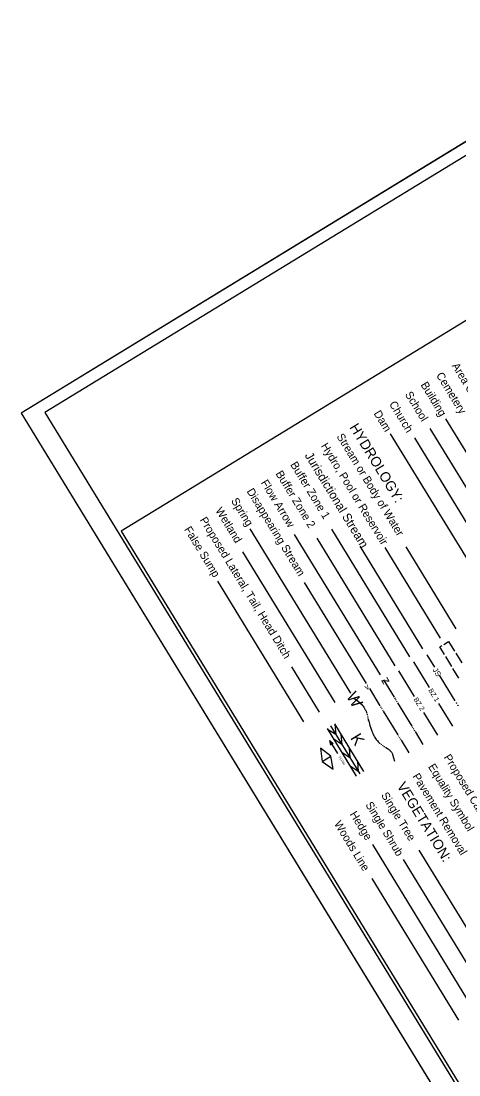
# Model space of a CAD drawing. Extents: x 1750583 to 1791140, y 783580 to 827376.
# Drawn here: x 1750583 to 1755844, y 799616 to 812289 of the extents above; entities that cross this region are included whole.
import ezdxf

# ---------------------------------------------------------------- set-up
doc = ezdxf.new("R2010")
doc.units = 0
for name, color, linetype in [('Sheet Cutting Line CELL', 7, 'Continuous'), ('Sheet Plot Border Inside CELL', 7, 'Continuous'), ('Sheet Plot Border Outside CELL', 7, 'Continuous'), ('Sheet Symbology CELL', 7, 'Continuous')]:
    doc.layers.add(name, color=color, linetype=linetype)

msp = doc.modelspace()

# ---------------------------------------------------------------- linework, layer by layer
at = {"layer": 'Sheet Cutting Line CELL'}
for p, q in [((1760908, 813883), (1750583, 807575)), ((1750583, 807575), (1760241, 791768))]:
    msp.add_line(p, q, dxfattribs=at)
at = {"layer": 'Sheet Plot Border Inside CELL'}
msp.add_lwpolyline([(1750868, 807581), (1760426, 791939), (1770330, 797990), (1760772, 813633)], close=True, dxfattribs=at)
at = {"layer": 'Sheet Plot Border Outside CELL'}
msp.add_lwpolyline([(1750583, 807575), (1760241, 791768), (1770566, 798076), (1760908, 813883)], close=True, dxfattribs=at)
at = {"layer": 'Sheet Symbology CELL'}
for p, q in [((1756879, 805555), (1755688, 807505)), ((1756316, 805211), (1755023, 807327)), ((1756692, 805441), (1755500, 807390)), ((1756504, 805326), (1755313, 807276)), ((1754544, 804207), (1753337, 806183)), ((1755256, 804642), (1754317, 806180)), ((1754902, 804426), (1753870, 806114)), ((1755079, 804534), (1754140, 806071)), ((1754356, 804093), (1753248, 805906)), ((1755412, 804738), (1754657, 805973)), ((1755624, 804867), (1754957, 805960)), ((1755812, 804982), (1755210, 805968)), ((1753981, 803863), (1752947, 805555)), ((1754732, 804322), (1753989, 805538)), ((1755661, 804792), (1755720, 804828)), ((1755720, 804828), (1755792, 804711)), ((1755757, 804529), (1755685, 804646)), ((1755806, 804687), (1755878, 804570)), ((1754168, 803978), (1753835, 804524)), ((1755297, 804584), (1755485, 804276)), ((1755119, 804475), (1755307, 804167)), ((1755843, 804388), (1755771, 804505)), ((1754769, 804261), (1754895, 804054)), ((1754939, 804365), (1755065, 804158)), ((1755071, 804149), (1755077, 804139)), ((1755083, 804130), (1755088, 804121)), ((1754901, 804045), (1754907, 804035)), ((1754913, 804026), (1754918, 804017)), ((1754924, 804007), (1754930, 803998)), ((1755094, 804111), (1755100, 804102)), ((1755106, 804092), (1755278, 803811)), ((1755771, 803809), (1755602, 804084)), ((1754749, 803913), (1754751, 803902)), ((1754935, 803989), (1755108, 803707)), ((1755592, 803701), (1755424, 803976)), ((1754260, 803782), (1754609, 803210)), ((1754365, 803709), (1754266, 803771)), ((1754302, 803812), (1754653, 803236)), ((1754348, 803837), (1754698, 803264)), ((1754353, 803828), (1754365, 803709)), ((1755283, 803801), (1755289, 803792)), ((1755295, 803783), (1755301, 803773)), ((1755306, 803764), (1755312, 803754)), ((1754290, 803637), (1754386, 803481)), ((1754290, 803637), (1754331, 803600)), ((1754290, 803637), (1754300, 803581)), ((1754437, 803589), (1754339, 803652)), ((1754426, 803709), (1754437, 803589)), ((1755113, 803698), (1755119, 803688)), ((1755125, 803679), (1755130, 803669)), ((1755136, 803660), (1755142, 803651)), ((1755148, 803641), (1755242, 803487)), ((1755318, 803745), (1755412, 803590)), ((1754306, 803449), (1754179, 803546)), ((1754179, 803546), (1754202, 803386)), ((1754524, 803550), (1754535, 803430)), ((1754906, 803594), (1754915, 803588)), ((1754924, 803581), (1754932, 803575)), ((1754202, 803386), (1754306, 803449)), ((1754202, 803386), (1754331, 803292)), ((1754331, 803292), (1754306, 803449)), ((1754535, 803430), (1754437, 803492)), ((1754625, 803383), (1754635, 803266)), ((1754635, 803266), (1754538, 803327)), ((1756029, 800391), (1754809, 802387)), ((1756405, 800620), (1755366, 802320)), ((1756217, 800505), (1755178, 802206)), ((1755841, 800276), (1754803, 801976))]:
    msp.add_line(p, q, dxfattribs=at)
msp.add_lwpolyline([(1770234, 798093), (1761631, 812173), (1751785, 806156), (1760388, 792077)], close=True, dxfattribs=at)
for points in [[(1755671, 804670), (1755614, 804763), (1755637, 804778)], [(1755457, 804668), (1755549, 804518)], [(1755607, 804423), (1755687, 804292)], [(1755687, 804292), (1755796, 804113)], [(1754581, 804146), (1754609, 804126), (1754636, 804106), (1754643, 804101), (1754654, 804092), (1754662, 804084), (1754674, 804073), (1754685, 804060), (1754693, 804049), (1754701, 804040), (1754706, 804031), (1754711, 804023), (1754719, 804008), (1754724, 803997), (1754728, 803989), (1754733, 803976), (1754736, 803967)], [(1754739, 803956), (1754740, 803951), (1754742, 803945)], [(1754744, 803935), (1754745, 803930), (1754746, 803924)], [(1754754, 803892), (1754755, 803883), (1754760, 803868), (1754768, 803838), (1754775, 803816), (1754786, 803784), (1754798, 803751), (1754805, 803734), (1754811, 803718), (1754817, 803705), (1754823, 803694), (1754828, 803684), (1754833, 803675), (1754842, 803661), (1754850, 803650), (1754856, 803643), (1754865, 803632), (1754875, 803621), (1754883, 803614), (1754890, 803607), (1754897, 803601)], [(1754941, 803568), (1754943, 803567), (1754950, 803562)], [(1754960, 803556), (1754965, 803553), (1754986, 803540), (1754996, 803534), (1755006, 803527), (1755013, 803521), (1755019, 803515), (1755023, 803510), (1755027, 803505), (1755034, 803497), (1755038, 803490), (1755040, 803484), (1755044, 803476), (1755047, 803468), (1755058, 803429), (1755069, 803390)]]:
    msp.add_lwpolyline(points, dxfattribs=at)
for centre in [(1755815, 804087), (1755832, 804060)]:
    msp.add_ellipse(centre, major_axis=(1.85, 1.13), ratio=0.938496, dxfattribs=at)

# ---------------------------------------------------------------- texts
for s, height, rotation, p in [('Cemetery', 96.3, 301.4249, (1755567, 808030)), ('Area Outline', 96.25, 301.4249, (1755755, 808144)), ('Building', 96.3, 301.4249, (1755380, 807915)), ('School', 96.3, 301.4249, (1755192, 807800)), ('Church', 96.3, 301.4249, (1755002, 807684)), ('Dam', 96.3, 301.4249, (1754816, 807571)), ('HYDROLOGY:', 121, 301.4249, (1754525, 807404)), ('Stream or Body of Water', 96.25, 301.4249, (1754370, 807294)), ('Hydro, Pool or Reservoir', 96.25, 301.4249, (1754182, 807180)), ('Jurisdictional Stream', 106.11, 301.4249, (1753987, 807065)), ('Buffer Zone 1', 96.25, 301.4249, (1753814, 806955)), ('Buffer Zone 2', 96.25, 301.4249, (1753637, 806847)), ('Disappearing Stream', 96.25, 301.4249, (1753290, 806635)), ('Flow Arrow', 96.3, 301.4249, (1753460, 806738)), ('Spring', 96.3, 301.4249, (1753102, 806520)), ('Wetland', 96.3, 301.4249, (1752914, 806405)), ('Proposed Lateral, Tail, Head Ditch', 96.25, 301.4249, (1752726, 806290)), ('False Sump', 96.3, 301.4249, (1752539, 806176)), ('z', 110, 121.425, (1755015, 804346)), ('JS', 65, 301.4249, (1755524, 804488)), ('v', 72.6, 31.1841, (1754734, 804240)), ('BZ 1', 58.5, 301.4249, (1755474, 804241)), ('W', 140, 301.4249, (1754485, 804169)), ('BZ 2', 58.5, 301.4249, (1755297, 804133)), ('K', 140, 301.4249, (1754534, 803668)), ('FLOW', 28.5, 301.4249, (1754396, 803436)), ('Proposed Cable Guiderail', 96.25, 301.4249, (1755658, 803436)), ('Pavement Removal', 96.25, 301.4249, (1755282, 803207)), ('Equality Symbol', 96.25, 301.4249, (1755470, 803322)), ('VEGETATION:', 121, 301.4249, (1755094, 803092)), ('Single Tree', 96.25, 301.4249, (1754905, 802980)), ('Single Shrub', 96.25, 301.4249, (1754717, 802865)), ('Hedge', 96.3, 301.4249, (1754529, 802751)), ('Woods Line', 96.3, 301.4249, (1754341, 802636))]:
    msp.add_text(s, height=height, rotation=rotation, dxfattribs=at).set_placement(p)

doc.saveas('drawing.dxf')
